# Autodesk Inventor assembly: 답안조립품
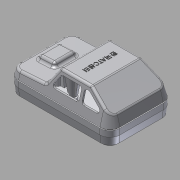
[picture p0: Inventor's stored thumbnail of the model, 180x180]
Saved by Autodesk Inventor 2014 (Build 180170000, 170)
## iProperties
Created: 2015-05
Part Number: 답안조립품
Document SubType Name: Assembly
Designer: Administrator
Author: Administrator
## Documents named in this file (5)
- C:\Documents and Settings\Administrator\바탕 화면\450508V1045\답안조립품.iam
- C:\Documents and Settings\Administrator\바탕 화면\450508V1045\본체.ipt
- C:\Documents and Settings\Administrator\바탕 화면\450508V1045\커버.ipt
- C:\Documents and Settings\Administrator\바탕 화면\450508V1045\바퀴고정부.ipt
- C:\Documents and Settings\Administrator\바탕 화면\450508V1045\바퀴.ipt
